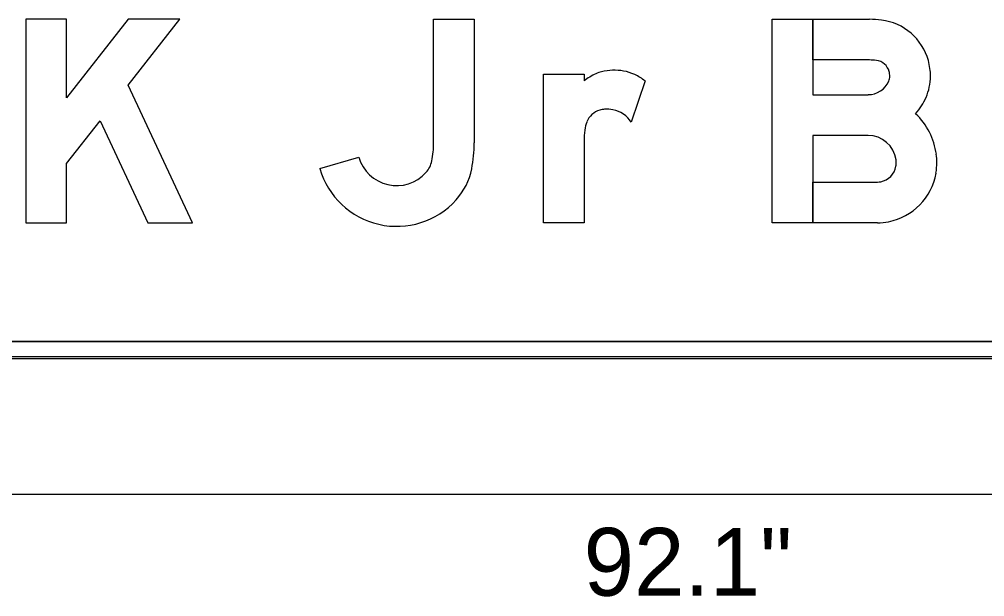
# Model space of a CAD drawing. Extents: x 1374 to 1480, y 568 to 638.
# Drawn here: x 1417.677 to 1420.051, y 598.164 to 599.583 of the extents above; entities that cross this region are included whole.
import ezdxf

# ---------------------------------------------------------------- set-up
doc = ezdxf.new("R2010")
doc.units = 0
for name, color, linetype in [('GSBWFill', 7, 'Continuous'), ('GSColorFill', 7, 'Continuous'), ('GSDims', 7, 'Continuous'), ('GSOutline', 7, 'Continuous')]:
    doc.layers.add(name, color=color, linetype=linetype)

msp = doc.modelspace()

# ---------------------------------------------------------------- linework, layer by layer
at = {"layer": 'GSBWFill'}
for p, q in [((1419.2156, 599.4316), (1419.1817, 599.3299)), ((1423.7331, 598.7912), (1414.9835, 598.7912)), ((1414.8581, 598.7496), (1423.8581, 598.7496)), ((1414.9835, 598.7496), (1423.7331, 598.7496))]:
    msp.add_line(p, q, dxfattribs=at)
msp.add_lwpolyline([(1417.6931, 599.0829), (1417.7931, 599.0829), (1417.7931, 599.2283), (1417.8753, 599.333), (1417.9927, 599.0829), (1418.1031, 599.0829), (1417.9444, 599.421), (1418.0715, 599.5829), (1417.9443, 599.5829), (1417.7931, 599.3902), (1417.7931, 599.5829), (1417.6931, 599.5829)], close=True, dxfattribs=at)
for points in [[(1418.6956, 599.279), (1418.6956, 599.5829), (1418.7956, 599.5829), (1418.7956, 599.279)], [(1419.7639, 599.2976), (1419.6281, 599.2976), (1419.6281, 599.0829), (1419.5281, 599.0829), (1419.5281, 599.5829), (1419.6281, 599.5829), (1419.6281, 599.3976), (1419.7639, 599.3976)], [(1419.767, 599.4829), (1419.6281, 599.4829), (1419.6281, 599.5829), (1419.767, 599.5829)], [(1419.0656, 599.2847), (1419.0656, 599.0829), (1418.9656, 599.0829), (1418.9656, 599.4479), (1419.0656, 599.4479), (1419.0656, 599.4316)], [(1418.4156, 599.2159), (1418.5116, 599.244)], [(1419.787, 599.0829), (1419.6281, 599.0829), (1419.6281, 599.1829), (1419.787, 599.1829)]]:
    msp.add_lwpolyline(points, dxfattribs=at)
for centre, major_axis, ratio, start_param, end_param in [((1419.767, 599.3423), (0, 0.2406), 0.999994, 6.158944, 6.283185), ((1419.7798, 599.4449), (0, 0.1372), 0.999994, 4.980924, 6.158944), ((1419.767, 599.3423), (0, 0.1406), 0.999994, 6.158944, 6.283185), ((1419.7798, 599.4449), (0, 0.0372), 0.999994, 4.980924, 6.158944), ((1419.7727, 599.4429), (0, 0.1446), 0.999994, 4.712389, 4.980924), ((1419.1661, 599.2983), (0, 0.1669), 0.99999, 0.443663, 0.646229), ((1419.1267, 599.3813), (0, 0.075), 0.99999, 0.24142, 0.443663), ((1419.1395, 599.3291), (0, 0.1287), 0.99999, 6.103268, 6.524606), ((1419.1424, 599.3451), (0, 0.1125), 0.99999, 5.846069, 6.103268), ((1419.1309, 599.3205), (0, 0.1396), 0.99999, 5.631644, 5.846069), ((1419.7727, 599.4429), (0, 0.0446), 0.999994, 4.712389, 4.980924), ((1419.7639, 599.4531), (0, 0.0554), 0.999994, 3.141593, 4.302517), ((1419.7872, 599.4429), (0, 0.03), 0.999994, 4.302517, 4.712389), ((1419.7872, 599.4429), (0, 0.13), 0.999994, 4.302517, 4.712389), ((1419.7639, 599.4531), (0, 0.1554), 0.999994, 3.993826, 4.302517), ((1419.1187, 599.3119), (0, 0.05), 0.99999, 0.293855, 1.188904), ((1419.1197, 599.3086), (0, 0.0534), 0.99999, 0.067293, 0.293855), ((1419.1215, 599.2821), (0, 0.08), 0.99999, 6.094384, 6.350479), ((1419.1236, 599.2931), (0, 0.0688), 0.99999, 5.27661, 6.094384), ((1419.7639, 599.2282), (0, 0.1694), 0.999994, 4.848927, 5.520752), ((1419.1448, 599.3014), (0, 0.0781), 0.99999, 1.188904, 1.450084), ((1419.2776, 599.2844), (0, 0.2119), 0.99999, 1.445958, 1.569673), ((1418.4699, 599.279), (0, 0.2257), 0.999994, 4.51573, 4.712389), ((1418.4699, 599.279), (0, 0.3257), 0.999994, 4.51573, 4.712389), ((1419.7639, 599.2282), (0, 0.0694), 0.999994, 4.848927, 6.283185), ((1418.6048, 599.2712), (0, 0.0971), 0.999994, 1.855303, 3.977825), ((1418.6319, 599.2467), (0, 0.0605), 0.999994, 3.977825, 4.51573), ((1419.7806, 599.2308), (0, 0.0525), 0.999994, 4.539563, 4.712389), ((1419.7824, 599.2308), (0, 0.0507), 0.999994, 4.712389, 4.848927), ((1419.7806, 599.2308), (0, 0.1525), 0.999994, 4.539563, 4.712389), ((1419.7824, 599.2308), (0, 0.1507), 0.999994, 4.712389, 4.848927), ((1418.6048, 599.2712), (0, 0.1971), 0.999994, 1.855303, 3.977825), ((1418.6319, 599.2467), (0, 0.1605), 0.999994, 3.977825, 4.51573), ((1419.786, 599.2299), (0, 0.0471), 0.999994, 3.334454, 4.539563), ((1419.787, 599.2248), (0, 0.0419), 0.999994, 3.141593, 3.334454), ((1419.786, 599.2299), (0, 0.1471), 0.999994, 3.334454, 4.539563), ((1419.787, 599.2248), (0, 0.1419), 0.999994, 3.141593, 3.334454)]:
    msp.add_ellipse(centre, major_axis=major_axis, ratio=ratio, start_param=start_param, end_param=end_param, dxfattribs=at)
at = {"layer": 'GSColorFill'}
for p, q in [((1419.2156, 599.4316), (1419.1817, 599.3299)), ((1423.7331, 598.7912), (1414.9835, 598.7912)), ((1423.854, 598.7537), (1414.8581, 598.7537)), ((1414.8581, 598.7496), (1423.8581, 598.7496)), ((1414.8581, 598.7496), (1423.8581, 598.7496)), ((1414.9835, 598.7496), (1423.7331, 598.7496))]:
    msp.add_line(p, q, dxfattribs=at)
msp.add_lwpolyline([(1417.6931, 599.0829), (1417.7931, 599.0829), (1417.7931, 599.2283), (1417.8753, 599.333), (1417.9927, 599.0829), (1418.1031, 599.0829), (1417.9444, 599.421), (1418.0715, 599.5829), (1417.9443, 599.5829), (1417.7931, 599.3902), (1417.7931, 599.5829), (1417.6931, 599.5829)], close=True, dxfattribs=at)
for points in [[(1418.6956, 599.279), (1418.6956, 599.5829), (1418.7956, 599.5829), (1418.7956, 599.279)], [(1419.7639, 599.2976), (1419.6281, 599.2976), (1419.6281, 599.0829), (1419.5281, 599.0829), (1419.5281, 599.5829), (1419.6281, 599.5829), (1419.6281, 599.3976), (1419.7639, 599.3976)], [(1419.767, 599.4829), (1419.6281, 599.4829), (1419.6281, 599.5829), (1419.767, 599.5829)], [(1419.0656, 599.2847), (1419.0656, 599.0829), (1418.9656, 599.0829), (1418.9656, 599.4479), (1419.0656, 599.4479), (1419.0656, 599.4316)], [(1418.4156, 599.2159), (1418.5116, 599.244)], [(1419.787, 599.0829), (1419.6281, 599.0829), (1419.6281, 599.1829), (1419.787, 599.1829)]]:
    msp.add_lwpolyline(points, dxfattribs=at)
for centre, major_axis, ratio, start_param, end_param in [((1419.767, 599.3423), (0, 0.2406), 0.999994, 6.158944, 6.283185), ((1419.7798, 599.4449), (0, 0.1372), 0.999994, 4.980924, 6.158944), ((1419.767, 599.3423), (0, 0.1406), 0.999994, 6.158944, 6.283185), ((1419.7798, 599.4449), (0, 0.0372), 0.999994, 4.980924, 6.158944), ((1419.7727, 599.4429), (0, 0.1446), 0.999994, 4.712389, 4.980924), ((1419.1661, 599.2983), (0, 0.1669), 0.99999, 0.443663, 0.646229), ((1419.1267, 599.3813), (0, 0.075), 0.99999, 0.24142, 0.443663), ((1419.1395, 599.3291), (0, 0.1287), 0.99999, 6.103268, 6.524606), ((1419.1424, 599.3451), (0, 0.1125), 0.99999, 5.846069, 6.103268), ((1419.1309, 599.3205), (0, 0.1396), 0.99999, 5.631644, 5.846069), ((1419.7727, 599.4429), (0, 0.0446), 0.999994, 4.712389, 4.980924), ((1419.7639, 599.4531), (0, 0.0554), 0.999994, 3.141593, 4.302517), ((1419.7872, 599.4429), (0, 0.03), 0.999994, 4.302517, 4.712389), ((1419.7872, 599.4429), (0, 0.13), 0.999994, 4.302517, 4.712389), ((1419.7639, 599.4531), (0, 0.1554), 0.999994, 3.993826, 4.302517), ((1419.1187, 599.3119), (0, 0.05), 0.99999, 0.293855, 1.188904), ((1419.1197, 599.3086), (0, 0.0534), 0.99999, 0.067293, 0.293855), ((1419.1215, 599.2821), (0, 0.08), 0.99999, 6.094384, 6.350479), ((1419.1236, 599.2931), (0, 0.0688), 0.99999, 5.27661, 6.094384), ((1419.7639, 599.2282), (0, 0.1694), 0.999994, 4.848927, 5.520752), ((1419.1448, 599.3014), (0, 0.0781), 0.99999, 1.188904, 1.450084), ((1419.2776, 599.2844), (0, 0.2119), 0.99999, 1.445958, 1.569673), ((1418.4699, 599.279), (0, 0.2257), 0.999994, 4.51573, 4.712389), ((1418.4699, 599.279), (0, 0.3257), 0.999994, 4.51573, 4.712389), ((1419.7639, 599.2282), (0, 0.0694), 0.999994, 4.848927, 6.283185), ((1418.6048, 599.2712), (0, 0.0971), 0.999994, 1.855303, 3.977825), ((1418.6319, 599.2467), (0, 0.0605), 0.999994, 3.977825, 4.51573), ((1419.7806, 599.2308), (0, 0.0525), 0.999994, 4.539563, 4.712389), ((1419.7824, 599.2308), (0, 0.0507), 0.999994, 4.712389, 4.848927), ((1419.7806, 599.2308), (0, 0.1525), 0.999994, 4.539563, 4.712389), ((1419.7824, 599.2308), (0, 0.1507), 0.999994, 4.712389, 4.848927), ((1418.6048, 599.2712), (0, 0.1971), 0.999994, 1.855303, 3.977825), ((1418.6319, 599.2467), (0, 0.1605), 0.999994, 3.977825, 4.51573), ((1419.786, 599.2299), (0, 0.0471), 0.999994, 3.334454, 4.539563), ((1419.787, 599.2248), (0, 0.0419), 0.999994, 3.141593, 3.334454), ((1419.786, 599.2299), (0, 0.1471), 0.999994, 3.334454, 4.539563), ((1419.787, 599.2248), (0, 0.1419), 0.999994, 3.141593, 3.334454)]:
    msp.add_ellipse(centre, major_axis=major_axis, ratio=ratio, start_param=start_param, end_param=end_param, dxfattribs=at)
at = {"layer": 'GSDims'}
msp.add_line((1415.5206, 598.4162), (1423.1956, 598.4162), dxfattribs=at)
at = {"layer": 'GSOutline'}
for p, q in [((1419.2156, 599.4316), (1419.1817, 599.3299)), ((1414.9831, 598.7912), (1423.7331, 598.7912)), ((1414.8581, 598.7496), (1423.8581, 598.7496)), ((1414.9831, 598.7496), (1423.7331, 598.7496))]:
    msp.add_line(p, q, dxfattribs=at)
msp.add_lwpolyline([(1417.6931, 599.0829), (1417.7931, 599.0829), (1417.7931, 599.2283), (1417.8753, 599.333), (1417.9927, 599.0829), (1418.1031, 599.0829), (1417.9444, 599.421), (1418.0715, 599.5829), (1417.9443, 599.5829), (1417.7931, 599.3902), (1417.7931, 599.5829), (1417.6931, 599.5829)], close=True, dxfattribs=at)
for points in [[(1418.6956, 599.279), (1418.6956, 599.5829), (1418.7956, 599.5829), (1418.7956, 599.279)], [(1419.787, 599.0829), (1419.5281, 599.0829), (1419.5281, 599.5829), (1419.767, 599.5829)], [(1419.767, 599.4829), (1419.6281, 599.4829), (1419.6281, 599.3976), (1419.7639, 599.3976)], [(1419.0656, 599.2847), (1419.0656, 599.0829), (1418.9656, 599.0829), (1418.9656, 599.4479), (1419.0656, 599.4479), (1419.0656, 599.4316)], [(1419.7639, 599.2976), (1419.6281, 599.2976), (1419.6281, 599.1829)], [(1418.4156, 599.2159), (1418.5116, 599.244)], [(1419.6281, 599.1829), (1419.787, 599.1829)]]:
    msp.add_lwpolyline(points, dxfattribs=at)
for centre, major_axis, ratio, start_param, end_param in [((1419.767, 599.3423), (0, 0.2406), 0.999994, 6.158944, 6.283185), ((1419.7798, 599.4449), (0, 0.1372), 0.999994, 4.980924, 6.158944), ((1419.767, 599.3423), (0, 0.1406), 0.999994, 6.158944, 6.283185), ((1419.7798, 599.4449), (0, 0.0372), 0.999994, 4.980924, 6.158944), ((1419.7727, 599.4429), (0, 0.1446), 0.999994, 4.712389, 4.980924), ((1419.1661, 599.2983), (0, 0.1669), 0.99999, 0.443663, 0.646229), ((1419.1267, 599.3813), (0, 0.075), 0.99999, 0.24142, 0.443663), ((1419.1395, 599.3291), (0, 0.1287), 0.99999, 6.103268, 6.524606), ((1419.1424, 599.3451), (0, 0.1125), 0.99999, 5.846069, 6.103268), ((1419.1309, 599.3205), (0, 0.1396), 0.99999, 5.631644, 5.846069), ((1419.7727, 599.4429), (0, 0.0446), 0.999994, 4.712389, 4.980924), ((1419.7639, 599.4531), (0, 0.0554), 0.999994, 3.141593, 4.302517), ((1419.7872, 599.4429), (0, 0.03), 0.999994, 4.302517, 4.712389), ((1419.7872, 599.4429), (0, 0.13), 0.999994, 4.302517, 4.712389), ((1419.7639, 599.4531), (0, 0.1554), 0.999994, 3.993826, 4.302517), ((1419.1187, 599.3119), (0, 0.05), 0.99999, 0.293855, 1.188904), ((1419.1197, 599.3086), (0, 0.0534), 0.99999, 0.067293, 0.293855), ((1419.1215, 599.2821), (0, 0.08), 0.99999, 6.094384, 6.350479), ((1419.1236, 599.2931), (0, 0.0688), 0.99999, 5.27661, 6.094384), ((1419.7639, 599.2282), (0, 0.1694), 0.999994, 4.848927, 5.520752), ((1419.1448, 599.3014), (0, 0.0781), 0.99999, 1.188904, 1.450084), ((1419.2776, 599.2844), (0, 0.2119), 0.99999, 1.445958, 1.569673), ((1418.4699, 599.279), (0, 0.2257), 0.999994, 4.51573, 4.712389), ((1418.4699, 599.279), (0, 0.3257), 0.999994, 4.51573, 4.712389), ((1419.7639, 599.2282), (0, 0.0694), 0.999994, 4.848927, 6.283185), ((1418.6048, 599.2712), (0, 0.0971), 0.999994, 1.855303, 3.977825), ((1418.6319, 599.2467), (0, 0.0605), 0.999994, 3.977825, 4.51573), ((1419.7806, 599.2308), (0, 0.0525), 0.999994, 4.539563, 4.712389), ((1419.7824, 599.2308), (0, 0.0507), 0.999994, 4.712389, 4.848927), ((1419.7806, 599.2308), (0, 0.1525), 0.999994, 4.539563, 4.712389), ((1419.7824, 599.2308), (0, 0.1507), 0.999994, 4.712389, 4.848927), ((1418.6048, 599.2712), (0, 0.1971), 0.999994, 1.855303, 3.977825), ((1418.6319, 599.2467), (0, 0.1605), 0.999994, 3.977825, 4.51573), ((1419.786, 599.2299), (0, 0.0471), 0.999994, 3.334454, 4.539563), ((1419.787, 599.2248), (0, 0.0419), 0.999994, 3.141593, 3.334454), ((1419.786, 599.2299), (0, 0.1471), 0.999994, 3.334454, 4.539563), ((1419.787, 599.2248), (0, 0.1419), 0.999994, 3.141593, 3.334454)]:
    msp.add_ellipse(centre, major_axis=major_axis, ratio=ratio, start_param=start_param, end_param=end_param, dxfattribs=at)

# ---------------------------------------------------------------- texts
at = {"layer": 'GSDims'}
msp.add_text('92.1"', height=0.16667, dxfattribs=at).set_placement((1419.0645, 598.1662))

doc.saveas('drawing.dxf')
